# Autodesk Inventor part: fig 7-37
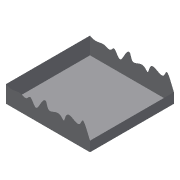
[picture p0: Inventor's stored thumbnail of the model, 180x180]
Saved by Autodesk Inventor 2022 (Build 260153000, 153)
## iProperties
Part Number: fig 7-37
Document SubType Name: Modeling
Created: 2002-12
Designer: deepak
Density: 1 g/cm^3
Material: Generic
Appearance: Default
Control State: 0
Master: False
Checked Out: False
Shininess: 64.0
Length Units: 11269
Angle Units: 11279
Time Units: 11290
Mass Units: 11283
Length Display Precision: 3
Angle Display Precision: 2
Compacted: True
Density: 0.0
Volumn: 0.0
Area: 0.0
PropertySet Name: Model Information
Author: deepak
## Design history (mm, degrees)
sketch "Sketch1"
  geometry: L1 (-32.188, 30.089)-(27.812, 30.089); L2 (27.812, 30.089)-(27.812, -29.911); L3 (27.812, -29.911)-(-32.188, -29.911); L4 (-32.188, -29.911)-(-32.188, 30.089)
  constraints: 8 end point, 2 parallel, 1 horizontal, 1 perpendicular
  dimensions: "d0" = 60 distance of L1.start L1.end; "d1" = 60 distance of L3.end L1.start
extrude "Extrusion1" new body sketch "Sketch1" stored distance "d2" = 20; taper "d3" = 0 deg
sketch "Sketch2"
  geometry: 17 further points
  constraints: 17 other
extrude_surface "ExtrusionSrf1" sketch "Sketch2" dims "d4" = 70, "d5" = 0
split "Split1"
delete_face "Delete Face1"
node "Sketch5"
body "Srf1"
body "Srf2"
